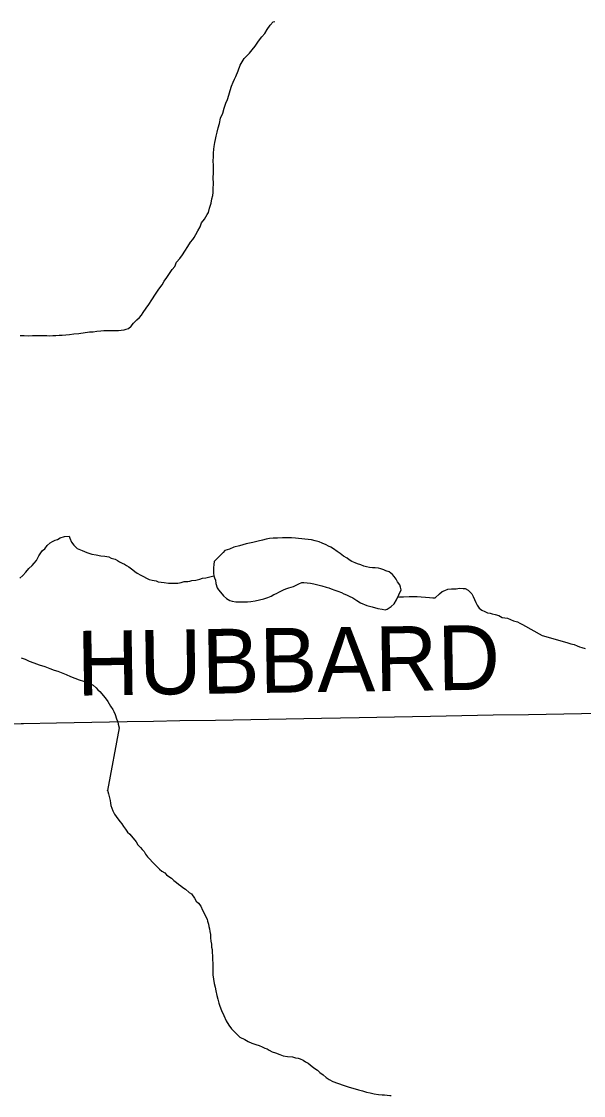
# Model space of a CAD drawing. Extents: x 103424 to 290657, y 38711 to 110967.
# Drawn here: x 165088 to 167708, y 45535 to 50546 of the extents above; entities that cross this region are included whole.
import ezdxf

# ---------------------------------------------------------------- set-up
doc = ezdxf.new("R2010")
doc.units = 0
for name, color, linetype in [('GM_X_Minor_Lake', 7, 'Continuous'), ('GM_X_Minor_River', 7, 'Continuous'), ('GM_X_Township_Road', 7, 'Continuous'), ('GM_X_Township_Road_Text', 7, 'Continuous')]:
    doc.layers.add(name, color=color, linetype=linetype)

msp = doc.modelspace()

# ---------------------------------------------------------------- linework, layer by layer
at = {"layer": 'GM_X_Minor_Lake'}
for points in [[(166070.5, 47840.4), (166086.7, 47838.7), (166117.1, 47837.4), (166129.2, 47837.6), (166141.3, 47837.9), (166157.5, 47840.3), (166177.6, 47842.7), (166197.7, 47847.2), (166217.8, 47851.7), (166235.9, 47858.1), (166251.9, 47864.5), (166263.9, 47872.9), (166275.9, 47877.2), (166287.9, 47883.5), (166299.9, 47889.8), (166309.9, 47894), (166319.9, 47898.3), (166334, 47902.6), (166356.1, 47909.2), (166368.1, 47915.5), (166380, 47921.8), (166394.1, 47928.2), (166404.2, 47928.4), (166434.5, 47925), (166450.8, 47921.3), (166469.1, 47917.7), (166487.4, 47912), (166507.7, 47906.4), (166519.9, 47902.6), (166532.1, 47898.9), (166548.4, 47893.2), (166562.7, 47887.4), (166579, 47881.7), (166591.2, 47875.9), (166603.5, 47870.1), (166615.7, 47864.3), (166632.1, 47856.6), (166650.5, 47844.9), (166668.9, 47833.2), (166697.5, 47821.7), (166721.9, 47814.1), (166748.3, 47806.7), (166768.6, 47803.1), (166782.8, 47801.3), (166792.9, 47803.6), (166810.8, 47816.1), (166824.7, 47828.5), (166836.4, 47846.9), (166857.6, 47893.8), (166855.3, 47905.9), (166851, 47917.9), (166840.6, 47931.8), (166834.3, 47943.8), (166826, 47955.7), (166817.7, 47965.6), (166801.3, 47977.4), (166787, 47983.1), (166776.8, 47986.9), (166762.5, 47992.7), (166752.4, 47994.5), (166736.2, 47996.1), (166724.1, 47995.9), (166709.9, 47997.6), (166695.6, 48001.3), (166683.4, 48005.1), (166669.2, 48010.8), (166654.9, 48014.6), (166642.7, 48020.3), (166628.4, 48026.1), (166616.1, 48033.9), (166605.9, 48041.8), (166589.5, 48051.5), (166573.1, 48063.2), (166558.7, 48073), (166542.3, 48084.8), (166530, 48092.6), (166519.7, 48098.4), (166507.5, 48104.2), (166489.1, 48111.9), (166474.9, 48117.6), (166456.6, 48123.3), (166440.3, 48127), (166424.1, 48128.6), (166379.5, 48133.7), (166365.4, 48135.5), (166347.1, 48137.1), (166326.9, 48136.6), (166304.7, 48136.1), (166280.5, 48135.6), (166260.3, 48135.2), (166244.1, 48132.8), (166228, 48130.5), (166212, 48126.1), (166191.8, 48121.6), (166165.7, 48115), (166135.5, 48108.3), (166103.4, 48099.5), (166077.3, 48092.9), (166057.2, 48084.4), (166035.1, 48077.8), (166027.3, 48067.6)], [(166027.3, 48067.6), (165985.7, 48026.3), (165984, 48012.1), (165982.3, 47995.9), (165982.6, 47983.8), (165982.8, 47971.7), (165985.1, 47959.7), (165987.4, 47949.6), (165991.6, 47939.6), (165994, 47923.5), (166000.5, 47903.5), (166006.7, 47893.5), (166015, 47883.6), (166029.6, 47865.7), (166044, 47854), (166058.3, 47844.2), (166070.5, 47840.4)]]:
    msp.add_lwpolyline(points, dxfattribs=at)
at = {"layer": 'GM_X_Minor_River'}
for points in [[(165354.5, 49090.5), (165404.9, 49097.6), (165421.1, 49098), (165439.2, 49100.4), (165457.3, 49102.8), (165471.5, 49103.1), (165485.6, 49103.4), (165501.8, 49103.8), (165513.9, 49104), (165528, 49104.3), (165540.2, 49104.6), (165552.3, 49104.9), (165566.4, 49107.2), (165576.4, 49109.4), (165586.5, 49113.7), (165598.4, 49124), (165610.2, 49138.4), (165626, 49152.9), (165637.9, 49165.3), (165647.8, 49175.6), (165655.6, 49187.9), (165669.3, 49208.3), (165681.1, 49224.7), (165694.7, 49247.2), (165712.4, 49273.9), (165728.1, 49296.4), (165743.8, 49316.9), (165753.5, 49333.3), (165765.3, 49351.7), (165777, 49370.1), (165790.7, 49388.6), (165802.6, 49403), (165810.2, 49423.3), (165826, 49439.8), (165837.8, 49456.2), (165849.5, 49474.6), (165863.2, 49495.1), (165874.9, 49515.6), (165886.8, 49527.9), (165892.6, 49538.2), (165900.4, 49552.5), (165910.2, 49568.8), (165919.9, 49587.2), (165927.6, 49605.5), (165941.3, 49624), (165947.2, 49634.2), (165953, 49644.4), (165958.9, 49654.6), (165964.5, 49675), (165972.1, 49697.3), (165975.7, 49717.6), (165979.4, 49733.8), (165981.1, 49748), (165980.8, 49764.1), (165982.2, 49790.4), (165981.7, 49816.6), (165983.2, 49838.9), (165982.9, 49855), (165982.5, 49873.2), (165982, 49895.4), (165983.6, 49913.6), (165983.2, 49931.7), (165984.9, 49949.9), (165986.6, 49962.1), (165988.3, 49980.3), (165992, 49994.5), (165995.7, 50010.7), (165999.3, 50029), (166005, 50049.3), (166010.6, 50069.6), (166016.1, 50093.9), (166025.7, 50118.3), (166033.3, 50140.7), (166040.9, 50165.1), (166048.6, 50181.4), (166054.2, 50201.7), (166059.8, 50224.1), (166067.5, 50244.4), (166075.2, 50262.7), (166080.9, 50277), (166086.7, 50289.2), (166098.3, 50315.7), (166107.8, 50342.2), (166125.4, 50372.8), (166151.1, 50397.6), (166162.9, 50414), (166176.7, 50430.5), (166192.3, 50453), (166208.1, 50473.5), (166221.9, 50490), (166233.6, 50508.4), (166247.3, 50528.9), (166261.2, 50543.3), (166269.2, 50545.5)], [(165081.9, 49080.5), (165100.1, 49080.9), (165120.3, 49079.4), (165138.5, 49079.8), (165158.7, 49080.2), (165180.9, 49080.7), (165205.2, 49081.2), (165219.3, 49079.5), (165233.5, 49079.8), (165247.6, 49080.1), (165263.8, 49082.5), (165277.9, 49082.8), (165294, 49083.1), (165312.2, 49085.5), (165332.3, 49088), (165354.5, 49090.5)], [(165079.9, 47948.1), (165093.8, 47960.5), (165107.6, 47977), (165121.4, 47993.4), (165137.2, 48007.9), (165147.1, 48018.2), (165157, 48030.5), (165168.6, 48053), (165178.4, 48067.3), (165186.3, 48077.6), (165196.2, 48085.9), (165208, 48100.3), (165221.9, 48112.7), (165231.9, 48118.9), (165243.9, 48125.3), (165255.9, 48129.6), (165267.9, 48135.9), (165288, 48142.4), (165310.1, 48144.9), (165312.4, 48134.8), (165320.8, 48116.8), (165331.2, 48102.9), (165347.8, 48087.1), (165370.2, 48077.5), (165392.6, 48067.9), (165415, 48060.3), (165435.3, 48056.8), (165457.6, 48053.2), (165475.9, 48051.6), (165494.1, 48047.9), (165506.4, 48042.1), (165524.7, 48036.5), (165534.9, 48030.6), (165545.1, 48024.8), (165557.4, 48019), (165567.6, 48013.2), (165577.8, 48007.4), (165588.1, 48001.5), (165606.6, 47987.8), (165616.8, 47979.9), (165627.1, 47972.1), (165643.5, 47962.3), (165655.7, 47956.6), (165670.1, 47948.8), (165682.3, 47943), (165696.5, 47939.3), (165714.8, 47935.6), (165725, 47931.8), (165739.2, 47930.1)], [(165739.2, 47930.1), (165753.4, 47928.4), (165773.7, 47924.8), (165793.8, 47925.2), (165816.1, 47925.7), (165832.2, 47928.1), (165846.3, 47932.4), (165862.4, 47932.8), (165872.5, 47935), (165882.5, 47937.3), (165900.7, 47939.7), (165918.8, 47944.1), (165930.8, 47948.4), (165946.9, 47950.8), (165985.1, 47959.7)], [(166842.2, 47859.1), (166850.2, 47861.3), (166868.4, 47861.7), (166894.7, 47862.3), (166916.9, 47862.8), (166933.1, 47863.1), (166951.3, 47861.5), (166971.5, 47859.9), (166989.8, 47858.3), (167006, 47856.6), (167016.1, 47856.9), (167035.9, 47875.5), (167049.8, 47885.9), (167061.8, 47890.2), (167075.8, 47896.5), (167092, 47898.9), (167102.1, 47899.1), (167114.2, 47899.4), (167130.3, 47901.7), (167146.5, 47900.1), (167156.6, 47900.3), (167170.9, 47892.5), (167187.5, 47874.7), (167193.8, 47862.7), (167200.2, 47848.7), (167206.5, 47834.8), (167212.8, 47822.8), (167221.2, 47808.8), (167233.6, 47799), (167247.8, 47793.3), (167260.1, 47787.5), (167272.3, 47785.7), (167282.4, 47781.9), (167296.7, 47778.2), (167312.9, 47774.5), (167329.3, 47764.8), (167353.6, 47761.2), (167367.9, 47755.5), (167382.2, 47749.8), (167400.5, 47744.1), (167410.7, 47738.2), (167422.9, 47732.5), (167514.7, 47681.6)], [(167514.7, 47681.6), (167630.3, 47648.4), (167648.5, 47642.5), (167664.6, 47638.6), (167678.8, 47632.6), (167688.9, 47628.6), (167701, 47624.7), (167715.2, 47620.8)], [(165085.8, 47576.8), (165104.2, 47571.2), (165122.6, 47561.5), (165145, 47553.9), (165169.4, 47544.3), (165195.9, 47536.8), (165220.3, 47527.3), (165240.7, 47519.6), (165257, 47513.9), (165273.3, 47508.2), (165295.7, 47498.6), (165316.1, 47489), (165336.5, 47481.3), (165356.9, 47473.7), (165377.2, 47468.1), (165391.5, 47462.3), (165403.7, 47458.6), (165422.1, 47448.9), (165436.5, 47437.1), (165442.8, 47427.1), (165453, 47419.3), (165477.9, 47389.5), (165490.4, 47373.7), (165496.7, 47361.7), (165503, 47351.7), (165513.4, 47335.8), (165517.7, 47325.8), (165524, 47311.8), (165530.5, 47291.8), (165536.9, 47277.8), (165539.1, 47267.7), (165542.9, 47250.8)], [(165542.9, 47250.8), (165489.2, 46957.8), (165489.2, 46959.8), (165493.6, 46941.7), (165498, 46923.7), (165500.3, 46911.6), (165502.6, 46899.5), (165504.9, 46887.5), (165509.2, 46875.5), (165513.4, 46863.5), (165521.9, 46847.5), (165536.5, 46825.6), (165546.9, 46811.7), (165555.2, 46801.8), (165563.5, 46789.8), (165571.9, 46777.9), (165582.3, 46764), (165592.6, 46754.1), (165621.7, 46718.4), (165630, 46704.5), (165642.4, 46692.7), (165650.7, 46682.7), (165659, 46672.8), (165665.3, 46660.8), (165675.7, 46649), (165686.1, 46637.1), (165698.5, 46623.2), (165710.9, 46611.4), (165721.2, 46599.5), (165731.5, 46591.6), (165741.8, 46581.8), (165756.1, 46574), (165764.4, 46564.1), (165774.7, 46556.2), (165787, 46548.4), (165797.3, 46538.6), (165809.6, 46528.7), (165819.9, 46520.9), (165830.2, 46513), (165840.5, 46505.2), (165852.8, 46497.4), (165869.3, 46481.6), (165879.5, 46475.7), (165894.1, 46455.9), (165902.4, 46441.9), (165912.8, 46432.1), (165923.2, 46418.2), (165931.6, 46400.2), (165938, 46388.2), (165944.3, 46374.2), (165952.7, 46358.2), (165955, 46348.2), (165959.3, 46334.2), (165961.6, 46324.1), (165963.8, 46312), (165966.1, 46300), (165968.4, 46285.9), (165968.8, 46269.8), (165971.1, 46255.7), (165973.4, 46241.6), (165973.7, 46227.5), (165976, 46215.4), (165976.2, 46205.3), (165978.7, 46183.2), (165979.7, 46136.8), (165980.1, 46118.6), (165980.5, 46098.4), (165983, 46078.3), (165985.4, 46058.2), (165989.9, 46040.1), (165994.3, 46024), (165998.8, 46001.9), (166003.2, 45983.9), (166007.6, 45965.8), (166012, 45951.8), (166020.5, 45931.7), (166031.1, 45907.8), (166041.7, 45883.8), (166054.3, 45863.8), (166066.8, 45845.9), (166081.2, 45832.1), (166093.6, 45820.3), (166106, 45806.4), (166128.5, 45796.8), (166144.9, 45787.1), (166161.2, 45779.4), (166179.5, 45773.7), (166195.8, 45768), (166210.1, 45762.2), (166222.3, 45756.5), (166232.5, 45752.6), (166242.7, 45746.8), (166257, 45739), (166271.3, 45733.3), (166291.7, 45725.7), (166308, 45720), (166328.3, 45716.4), (166350.5, 45714.8), (166364.8, 45711.1), (166376.9, 45709.3), (166387.1, 45705.5)], [(166387.1, 45705.5), (166401.4, 45699.8), (166411.6, 45691.9), (166423.9, 45686.1), (166442.4, 45670.4), (166454.8, 45660.6), (166467.1, 45652.7), (166479.4, 45642.9), (166493.8, 45631.1), (166508.2, 45619.3), (166522.6, 45609.6), (166538.9, 45599.8), (166587.8, 45582.7), (166610.2, 45575.1), (166626.5, 45571.4), (166642.7, 45565.7), (166659, 45562), (166677.3, 45556.4), (166695.6, 45550.7), (166713.9, 45547.1), (166732.1, 45543.4), (166752.4, 45539.8), (166768.6, 45538.2), (166780.8, 45538.4), (166792.9, 45536.7), (166805.1, 45534.9), (166811.1, 45535.1)]]:
    msp.add_lwpolyline(points, dxfattribs=at)
at = {"layer": 'GM_X_Township_Road'}
for points in [[(165096.2, 47270.2), (165250.5, 47273.1), (165415.6, 47276.1), (165580.6, 47279.1), (165703.5, 47281.4), (165826.4, 47283.7), (165991.4, 47286.7), (166156.5, 47289.7), (166321.5, 47292.8), (166486.5, 47295.8), (166574.3, 47297.5), (166662.1, 47299.1), (166827.2, 47302.1), (166910.5, 47303.7), (166993.9, 47305.2), (167140, 47308), (167286.1, 47310.6), (167451.2, 47313.1), (167616.2, 47315.6), (167781.2, 47318.1)], [(162829, 47248.8), (162853.7, 47238.8), (162906.1, 47234.4), (163005.7, 47236.1), (163105.4, 47237.9), (163270.4, 47239.9), (163435.5, 47241.9), (163600.6, 47243.9), (163706.9, 47245.3), (163813.2, 47246.6), (163957.6, 47250), (164102.1, 47253.4), (164267.1, 47256.2), (164432.2, 47258.9), (164597.2, 47261.6), (164758.9, 47264.3), (164920.5, 47267), (165085.5, 47270), (165096.2, 47270.2)]]:
    msp.add_lwpolyline(points, dxfattribs=at)

# ---------------------------------------------------------------- texts
at = {"layer": 'GM_X_Township_Road_Text'}
msp.add_text('HUBBARD', height=301.87, rotation=0.8424, dxfattribs=at).set_placement((165346.8, 47400.3))

doc.saveas('drawing.dxf')
